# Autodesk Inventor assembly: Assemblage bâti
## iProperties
Created: 2011-02
Part Number: Assemblage bâti
Document SubType Name: Assembly
Designer: eric
Norme de conversion: IGES 5.3
Nom du fichier: No Iges File Name specified
Préprocesseur: Autodesk Inventor 2011
Postprocesseur: Build: 342, Release: 2008 SP3 - Date: Tue 05/27/2008
Unités envoyées: MM
Incertitude: 0.01
Author: eric
